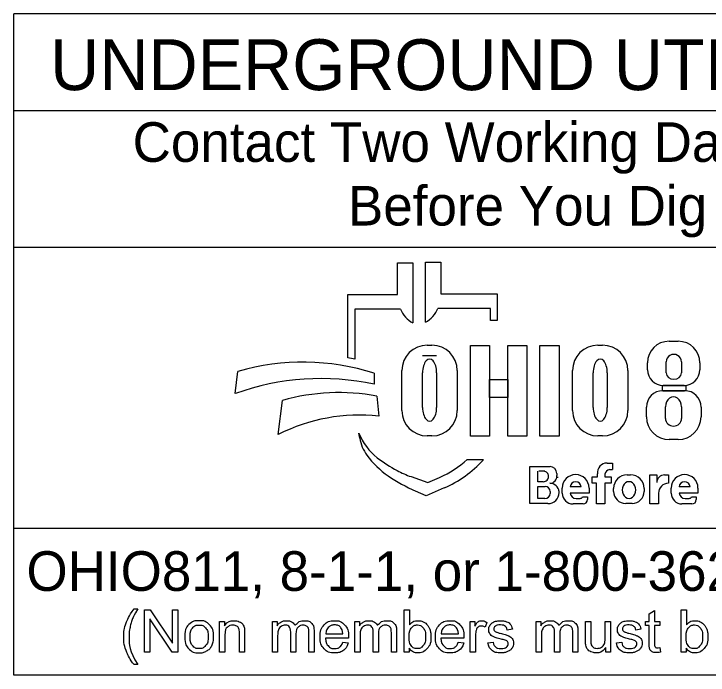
# Model space of a CAD drawing. Extents: x -0.3 to 41.5, y 0 to 22.
# Drawn here: x 2.978 to 5.431, y 2.345 to 4.682 of the extents above; entities that cross this region are included whole.
import ezdxf

# ---------------------------------------------------------------- set-up
doc = ezdxf.new("R2010")
doc.units = 0
doc.layers.add('GM_X_Section', color=7, linetype='Continuous')
doc.layers.add('SH_Cut_Line', color=7, linetype='Continuous')

msp = doc.modelspace()

# ---------------------------------------------------------------- linework, layer by layer
at = {"layer": 'GM_X_Section'}
for p, q in [((4.4329, 3.592), (4.4329, 3.8041)), ((4.4329, 3.8041), (4.4865, 3.8041)), ((4.4865, 3.8041), (4.4865, 3.6926)), ((4.3335, 3.6902), (4.3335, 3.8017)), ((4.3335, 3.8017), (4.3872, 3.8017)), ((4.3872, 3.8017), (4.3872, 3.5897)), ((4.1576, 3.4664), (4.1576, 3.6902)), ((4.1576, 3.6902), (4.3335, 3.6902)), ((4.4865, 3.6926), (4.6857, 3.6926)), ((4.6857, 3.6926), (4.6857, 3.5987)), ((4.1828, 3.6388), (4.1828, 3.4619)), ((4.3439, 3.6388), (4.1828, 3.6388)), ((4.6625, 3.6411), (4.4761, 3.6411)), ((4.6625, 3.5987), (4.6625, 3.6411)), ((4.6857, 3.5987), (4.6625, 3.5987)), ((4.4385, 3.5111), (4.4551, 3.5111)), ((5.0416, 3.5111), (5.0581, 3.5111)), ((5.2931, 3.5251), (5.3258, 3.5251)), ((4.4718, 3.474), (4.422, 3.474)), ((5.2168, 3.4244), (5.2168, 3.4487)), ((5.283, 3.4131), (5.283, 3.4524)), ((5.3371, 3.4524), (5.3371, 3.4131)), ((5.4022, 3.4487), (5.4022, 3.4244)), ((3.7602, 3.3401), (3.7696, 3.4182)), ((4.2509, 3.4117), (4.2509, 3.3729)), ((4.3491, 3.2796), (4.3491, 3.4216)), ((4.422, 3.291), (4.422, 3.4133)), ((4.4718, 3.4133), (4.4718, 3.291)), ((4.5445, 3.4216), (4.5445, 3.2796)), ((4.9521, 3.2796), (4.9521, 3.4216)), ((5.025, 3.291), (5.025, 3.4133)), ((5.0748, 3.4133), (5.0748, 3.291)), ((5.1476, 3.4216), (5.1476, 3.2796)), ((5.3462, 3.3684), (5.2728, 3.3684)), ((5.271, 3.3501), (5.3483, 3.3501)), ((3.912, 3.1955), (3.9267, 3.3157)), ((4.2608, 3.3311), (4.2671, 3.2601)), ((5.2131, 3.2582), (5.2131, 3.2923)), ((5.2806, 3.2523), (5.2806, 3.2932)), ((5.3374, 3.2932), (5.3374, 3.2523)), ((5.4062, 3.2923), (5.4062, 3.2582)), ((4.1997, 3.1826), (4.1967, 3.2005)), ((4.4551, 3.1901), (4.4385, 3.1901)), ((5.0581, 3.1901), (5.0416, 3.1901)), ((5.3252, 3.1773), (5.2941, 3.1773)), ((4.58, 3.1067), (4.6375, 3.1067)), ((5.0739, 3.0945), (5.0934, 3.0945)), ((5.0934, 3.0945), (5.0934, 3.0715)), ((4.8013, 2.951), (4.8013, 3.0817)), ((4.8013, 3.0817), (4.8725, 3.0817)), ((5.0934, 3.071), (5.0832, 3.071)), ((4.3816, 3.0464), (4.441, 3.0259)), ((4.441, 3.0259), (4.4821, 3.0437)), ((4.8293, 3.0282), (4.8293, 3.0652)), ((4.8545, 3.0652), (4.8332, 3.0652)), ((4.8963, 3.058), (4.8963, 3.0501)), ((5.0213, 3.0231), (5.0213, 3.0461)), ((5.0213, 3.0461), (5.0406, 3.0461)), ((5.0406, 3.0461), (5.0406, 3.0566)), ((5.0667, 3.0546), (5.0667, 3.0461)), ((5.0667, 3.0461), (5.0883, 3.0461)), ((5.0883, 3.0461), (5.0883, 3.0231)), ((5.1451, 3.0527), (5.1573, 3.0527)), ((5.2254, 2.9498), (5.2254, 3.0525)), ((5.2254, 3.0525), (5.2499, 3.0525)), ((5.2499, 3.0525), (5.2499, 3.0256)), ((5.2772, 3.0525), (5.291, 3.0525)), ((5.291, 3.0525), (5.291, 3.0228)), ((4.8487, 3.0282), (4.8293, 3.0282)), ((5.0362, 3.0231), (5.0213, 3.0231)), ((5.0362, 2.9498), (5.0362, 3.0231)), ((5.0883, 3.0231), (5.0667, 3.0231)), ((5.0667, 3.0231), (5.0667, 2.9498)), ((4.435, 2.9789), (4.3976, 2.9953)), ((4.4983, 3.0063), (4.435, 2.9789)), ((4.8293, 2.9688), (4.8293, 3.0117)), ((4.8293, 3.0117), (4.8548, 3.0117)), ((4.9159, 2.9878), (4.9159, 3.0062)), ((4.9824, 3.0102), (4.9439, 3.0102)), ((5.0104, 3.0062), (5.0104, 2.9885)), ((5.0973, 2.9941), (5.0973, 3.0049)), ((5.2051, 3.0049), (5.2051, 2.9941)), ((5.3008, 2.9878), (5.3008, 3.0062)), ((5.3674, 3.0102), (5.3288, 3.0102)), ((5.3953, 3.0062), (5.3953, 2.9885)), ((4.8729, 2.9936), (4.8729, 2.9872)), ((4.9043, 2.9907), (4.9043, 2.9903)), ((5.0104, 2.9885), (4.944, 2.9885)), ((4.9649, 2.9693), (4.979, 2.9693)), ((4.9876, 2.9748), (5.0045, 2.9748)), ((5.0045, 2.9748), (5.0045, 2.965)), ((5.2559, 2.9879), (5.2559, 2.9498)), ((5.3953, 2.9885), (5.3289, 2.9885)), ((5.3498, 2.9693), (5.3639, 2.9693)), ((5.3725, 2.9748), (5.3894, 2.9748)), ((5.3894, 2.9748), (5.3894, 2.965)), ((4.865, 2.951), (4.8013, 2.951)), ((4.8546, 2.9688), (4.8293, 2.9688)), ((4.9892, 2.9498), (4.9538, 2.9498)), ((5.0667, 2.9498), (5.0362, 2.9498)), ((5.1623, 2.9513), (5.1401, 2.9513)), ((5.2559, 2.9498), (5.2254, 2.9498)), ((5.3742, 2.9498), (5.3388, 2.9498))]:
    msp.add_line(p, q, dxfattribs=at)
for points in [[(4.591, 3.51), (4.6589, 3.51), (4.6589, 3.19), (4.591, 3.19)], [(4.7231, 3.51), (4.7911, 3.51), (4.7911, 3.19), (4.7231, 3.19)], [(4.8364, 3.51), (4.9052, 3.51), (4.9052, 3.19), (4.8364, 3.19)], [(4.6589, 3.3901), (4.7231, 3.3901), (4.7231, 3.3261), (4.6589, 3.3261)], [(5.2706, 3.3685), (5.3523, 3.3685), (5.3523, 3.35), (5.2706, 3.35)]]:
    msp.add_lwpolyline(points, close=True, dxfattribs=at)
for points in [[(3.4021, 2.5785), (3.4153, 2.5785)], [(3.4389, 2.4259), (3.4389, 2.576), (3.4592, 2.576), (3.5382, 2.4581), (3.5382, 2.576), (3.5572, 2.576), (3.5572, 2.4259), (3.5369, 2.4259), (3.4579, 2.5438), (3.4579, 2.4259), (3.4389, 2.4259)], [(4.3743, 2.4259), (4.3573, 2.4259), (4.3573, 2.576), (4.3757, 2.576), (4.3757, 2.5225)], [(5.2233, 2.4577), (5.2233, 2.5204), (5.2097, 2.5204), (5.2097, 2.5347), (5.2233, 2.5347), (5.2233, 2.5616), (5.2417, 2.5727), (5.2417, 2.5347), (5.2601, 2.5347), (5.2601, 2.5204), (5.2417, 2.5204), (5.2417, 2.4566)], [(5.3534, 2.4259), (5.3363, 2.4259), (5.3363, 2.576), (5.3548, 2.576), (5.3548, 2.5225)], [(3.7048, 2.4259), (3.7048, 2.5347), (3.7214, 2.5347), (3.7214, 2.5192)], [(3.8912, 2.4259), (3.8912, 2.5347), (3.9077, 2.5347), (3.9077, 2.5193)], [(4.1826, 2.4259), (4.1826, 2.5347), (4.1991, 2.5347), (4.1991, 2.5193)], [(4.5904, 2.4259), (4.5904, 2.5347), (4.607, 2.5347), (4.607, 2.5182)], [(4.6495, 2.5312), (4.643, 2.5142)], [(4.8236, 2.4259), (4.8236, 2.5347), (4.8401, 2.5347), (4.8401, 2.5193)], [(4.9979, 2.4673), (4.9979, 2.5347), (5.0164, 2.5347), (5.0164, 2.4744)], [(5.0676, 2.4764), (5.0676, 2.5347), (5.0861, 2.5347), (5.0861, 2.4259), (5.0696, 2.4259)], [(4.7394, 2.5066), (4.7213, 2.5041)], [(5.194, 2.5066), (5.1759, 2.5041)], [(3.7233, 2.4853), (3.7233, 2.4259), (3.7048, 2.4259)], [(3.7932, 2.4928), (3.7932, 2.4259), (3.7748, 2.4259), (3.7748, 2.492)], [(3.9097, 2.4823), (3.9097, 2.4259), (3.8912, 2.4259)], [(3.9743, 2.489), (3.9743, 2.4259), (3.9559, 2.4259), (3.9559, 2.4965)], [(4.0388, 2.5005), (4.0388, 2.4259), (4.0203, 2.4259), (4.0203, 2.4944)], [(4.0799, 2.4906), (4.1406, 2.4906)], [(4.201, 2.4823), (4.201, 2.4259), (4.1826, 2.4259)], [(4.2657, 2.489), (4.2657, 2.4259), (4.2473, 2.4259), (4.2473, 2.4965)], [(4.3301, 2.5005), (4.3301, 2.4259), (4.3117, 2.4259), (4.3117, 2.4944)], [(4.4879, 2.4906), (4.5486, 2.4906)], [(4.6088, 2.4829), (4.6088, 2.4259), (4.5904, 2.4259)], [(4.842, 2.4823), (4.842, 2.4259), (4.8236, 2.4259)], [(4.9067, 2.489), (4.9067, 2.4259), (4.8883, 2.4259), (4.8883, 2.4965)], [(4.9711, 2.5005), (4.9711, 2.4259), (4.9527, 2.4259), (4.9527, 2.4944)], [(4.16, 2.4755), (4.0788, 2.4755)], [(4.1404, 2.461), (4.1595, 2.4586)], [(4.568, 2.4755), (4.4868, 2.4755)], [(4.5484, 2.461), (4.5675, 2.4586)], [(4.653, 2.4584), (4.6712, 2.4612)], [(5.1076, 2.4584), (5.1258, 2.4612)], [(4.3743, 2.4395), (4.3743, 2.4259)], [(5.0696, 2.4259), (5.0696, 2.4419)], [(5.2601, 2.4423), (5.2628, 2.426)], [(5.3534, 2.4395), (5.3534, 2.4259)], [(3.4153, 2.3817), (3.4021, 2.3817)]]:
    msp.add_lwpolyline(points, dxfattribs=at)
for centre, radius, start, end in [((4.4353, 3.6756), 0.0985, 201.9296, 240.7469), ((4.3847, 3.6779), 0.0985, 299.2531, 338.0704), ((4.4385, 3.4216), 0.0895, 90, 180), ((4.4551, 3.4216), 0.0895, 0, 90), ((5.0416, 3.4216), 0.0895, 90, 180), ((5.0581, 3.4216), 0.0895, 0, 90), ((5.2931, 3.4487), 0.0763, 90, 180), ((5.3258, 3.4487), 0.0763, 0, 90), ((4.0295, 2.6574), 0.8191, 79.2074, 81.0007), ((3.9997, 2.6321), 0.8191, 72.1402, 106.3144), ((5.2728, 3.4244), 0.056, 180, 270), ((5.3462, 3.4244), 0.056, 270, 0), ((4.0628, 2.501), 0.8919, 77.8238, 109.8274), ((4.1267, 2.6113), 0.7322, 79.44, 105.8467), ((5.271, 3.2923), 0.0579, 90, 180), ((5.3483, 3.2923), 0.0579, 0, 90), ((4.1987, 2.6281), 0.6357, 83.8248, 116.8021), ((4.4385, 3.2796), 0.0895, 180, 270), ((4.4551, 3.2796), 0.0895, 270, 0), ((5.0416, 3.2796), 0.0895, 180, 270), ((5.0581, 3.2796), 0.0895, 270, 0), ((5.2941, 3.2582), 0.081, 180, 270), ((5.3252, 3.2582), 0.081, 270, 0), ((4.3841, 3.2726), 0.2008, 201.0457, 232.5314), ((4.341, 3.2067), 0.1433, 189.6817, 216.0884), ((4.4747, 3.3042), 0.3088, 216.0884, 235.7167), ((4.5766, 3.5239), 0.5173, 232.5314, 241.794), ((4.3387, 3.3742), 0.3602, 293.4582, 312.0712), ((4.3387, 3.3742), 0.401, 293.4582, 317.8286), ((5.0739, 3.061), 0.0335, 90, 187.5187), ((4.4914, 3.365), 0.3371, 241.794, 250.9821), ((4.8725, 3.058), 0.0238, 0, 90), ((5.0832, 3.0546), 0.0165, 90, 180), ((4.6412, 3.5484), 0.6044, 235.7167, 246.2325), ((4.8487, 3.047), 0.0187, 270, 2.0582), ((4.8505, 3.0483), 0.0169, 357.8325, 90), ((4.8721, 3.0472), 0.0243, 270, 6.6529), ((4.8827, 3.0458), 0.0175, 347.4023, 0), ((4.9631, 3.0062), 0.0473, 0, 180), ((5.1451, 3.0049), 0.0478, 90, 180), ((5.1573, 3.0049), 0.0478, 0, 90), ((5.2768, 3.0256), 0.0269, 89.2449, 180), ((5.3481, 3.0062), 0.0473, 0, 180), ((4.8722, 2.9908), 0.0321, 4.0748, 90), ((4.9632, 3.0092), 0.0193, 2.9632, 177.0368), ((5.2908, 2.9879), 0.0349, 89.6033, 180), ((5.3481, 3.0092), 0.0193, 2.9632, 177.0368), ((4.8548, 2.9936), 0.0181, 0, 90), ((4.8714, 2.9907), 0.033, 0, 11.7502), ((5.1401, 2.9941), 0.0428, 180, 270), ((5.1623, 2.9941), 0.0428, 270, 0), ((4.8546, 2.9872), 0.0184, 270, 0), ((4.865, 2.9903), 0.0393, 270, 0), ((4.9538, 2.9878), 0.038, 180, 270), ((4.9649, 2.9903), 0.021, 184.827, 270), ((4.979, 2.9787), 0.00938, 270, 335.9979), ((5.3388, 2.9878), 0.038, 180, 270), ((5.3498, 2.9903), 0.021, 184.827, 270), ((5.3639, 2.9787), 0.00938, 270, 335.9979), ((4.9892, 2.965), 0.0152, 270, 0), ((5.3742, 2.965), 0.0152, 270, 0)]:
    msp.add_arc(centre, radius, start, end, dxfattribs=at)
for centre, major_axis, ratio, start_param, end_param in [((4.4469, 3.4133), (0, 0.0484), 0.514403, 4.712389, 7.853982), ((5.0499, 3.4133), (0, 0.0484), 0.514403, 4.712389, 7.853982), ((5.31, 3.4524), (0.0271, 0), 0.969373, 0, 3.141593), ((5.31, 3.4131), (0.0271, 0), 0.818453, 3.141593, 6.283185), ((5.309, 3.2932), (0, 0.0358), 0.794529, 4.712389, 7.853982), ((4.4469, 3.291), (0, 0.0484), 0.514403, 1.570796, 4.712389), ((5.0499, 3.291), (0, 0.0484), 0.514403, 1.570796, 4.712389), ((5.309, 3.2523), (0.0284, 0), 0.959837, 3.141593, 6.283185), ((5.1517, 2.9995), (0, 0.029), 0.832186, 4.712389, 7.853982), ((5.1517, 2.9995), (0, 0.0302), 0.797287, 1.570796, 4.712389)]:
    msp.add_ellipse(centre, major_axis=major_axis, ratio=ratio, start_param=start_param, end_param=end_param, dxfattribs=at)
for points in [[(3.4021, 2.3817), (3.3869, 2.4009), (3.3763, 2.4268), (3.3657, 2.4526), (3.3657, 2.4802), (3.3657, 2.5046), (3.3736, 2.5269), (3.3829, 2.5528), (3.4021, 2.5785)], [(3.4153, 2.5785), (3.4029, 2.5572), (3.3989, 2.5481), (3.3927, 2.534), (3.3891, 2.5186), (3.3847, 2.4995), (3.3847, 2.4801), (3.3847, 2.4309), (3.4153, 2.3817)], [(3.5814, 2.4803), (3.5814, 2.5105), (3.5981, 2.525), (3.6122, 2.5371), (3.6323, 2.5371), (3.6547, 2.5371), (3.669, 2.5224), (3.6832, 2.5077), (3.6832, 2.4818), (3.6832, 2.4608), (3.6769, 2.4488), (3.6706, 2.4368), (3.6586, 2.4301), (3.6466, 2.4235), (3.6323, 2.4235), (3.6095, 2.4235), (3.5954, 2.4381), (3.5814, 2.4527), (3.5814, 2.4803)], [(3.7214, 2.5192), (3.7334, 2.5371), (3.756, 2.5371), (3.7659, 2.5371), (3.7741, 2.5336), (3.7823, 2.53), (3.7864, 2.5243), (3.7905, 2.5186), (3.7922, 2.5107), (3.7932, 2.5056), (3.7932, 2.4928)], [(3.9077, 2.5193), (3.9128, 2.5274), (3.9214, 2.5322), (3.9299, 2.5371), (3.9407, 2.5371), (3.9528, 2.5371), (3.9606, 2.5321), (3.9683, 2.527), (3.9715, 2.518), (3.9844, 2.5371), (4.0051, 2.5371), (4.0213, 2.5371), (4.03, 2.5281), (4.0388, 2.5192), (4.0388, 2.5005)], [(4.1595, 2.4586), (4.155, 2.4419), (4.1428, 2.4327), (4.1306, 2.4235), (4.1117, 2.4235), (4.0878, 2.4235), (4.0738, 2.4382), (4.0598, 2.4528), (4.0598, 2.4794), (4.0598, 2.5068), (4.074, 2.522), (4.0881, 2.5371), (4.1106, 2.5371), (4.1324, 2.5371), (4.1463, 2.5223), (4.1601, 2.5074), (4.1601, 2.4805), (4.1601, 2.4788), (4.16, 2.4755)], [(4.1991, 2.5193), (4.2042, 2.5274), (4.2127, 2.5322), (4.2212, 2.5371), (4.2321, 2.5371), (4.2442, 2.5371), (4.2519, 2.5321), (4.2597, 2.527), (4.2628, 2.518), (4.2758, 2.5371), (4.2965, 2.5371), (4.3127, 2.5371), (4.3214, 2.5281), (4.3301, 2.5192), (4.3301, 2.5005)], [(4.3757, 2.5225), (4.3874, 2.5371), (4.4055, 2.5371), (4.4155, 2.5371), (4.4245, 2.5331), (4.4335, 2.529), (4.4392, 2.5217), (4.445, 2.5144), (4.4483, 2.504), (4.4516, 2.4937), (4.4516, 2.4819), (4.4516, 2.454), (4.4378, 2.4387), (4.4239, 2.4235), (4.4046, 2.4235), (4.3853, 2.4235), (4.3743, 2.4395)], [(4.5675, 2.4586), (4.563, 2.4419), (4.5508, 2.4327), (4.5386, 2.4235), (4.5196, 2.4235), (4.4958, 2.4235), (4.4818, 2.4382), (4.4678, 2.4528), (4.4678, 2.4794), (4.4678, 2.5068), (4.482, 2.522), (4.4961, 2.5371), (4.5186, 2.5371), (4.5404, 2.5371), (4.5543, 2.5223), (4.5681, 2.5074), (4.5681, 2.4805), (4.5681, 2.4788), (4.568, 2.4755)], [(4.607, 2.5182), (4.6133, 2.5298), (4.6187, 2.5334), (4.6241, 2.5371), (4.6305, 2.5371), (4.6398, 2.5371), (4.6495, 2.5312)], [(4.6712, 2.4612), (4.6727, 2.4503), (4.6798, 2.4444), (4.6868, 2.4386), (4.6995, 2.4386), (4.7122, 2.4386), (4.7184, 2.4438), (4.7245, 2.4489), (4.7245, 2.4559), (4.7245, 2.4622), (4.7191, 2.4658), (4.7153, 2.4682), (4.7002, 2.472), (4.6799, 2.4771), (4.672, 2.4809), (4.6642, 2.4846), (4.6601, 2.4912), (4.6561, 2.4978), (4.6561, 2.5058), (4.6561, 2.5131), (4.6594, 2.5192), (4.6628, 2.5254), (4.6685, 2.5295), (4.6728, 2.5327), (4.6803, 2.5349), (4.6877, 2.5371), (4.6962, 2.5371), (4.709, 2.5371), (4.7187, 2.5334), (4.7284, 2.5297), (4.733, 2.5234), (4.7377, 2.5171), (4.7394, 2.5066)], [(4.8401, 2.5193), (4.8452, 2.5274), (4.8537, 2.5322), (4.8622, 2.5371), (4.8731, 2.5371), (4.8852, 2.5371), (4.8929, 2.5321), (4.9007, 2.527), (4.9038, 2.518), (4.9168, 2.5371), (4.9375, 2.5371), (4.9537, 2.5371), (4.9624, 2.5281), (4.9711, 2.5192), (4.9711, 2.5005)], [(5.1258, 2.4612), (5.1273, 2.4503), (5.1343, 2.4444), (5.1414, 2.4386), (5.154, 2.4386), (5.1668, 2.4386), (5.1729, 2.4438), (5.1791, 2.4489), (5.1791, 2.4559), (5.1791, 2.4622), (5.1736, 2.4658), (5.1698, 2.4682), (5.1548, 2.472), (5.1345, 2.4771), (5.1266, 2.4809), (5.1188, 2.4846), (5.1147, 2.4912), (5.1107, 2.4978), (5.1107, 2.5058), (5.1107, 2.5131), (5.114, 2.5192), (5.1173, 2.5254), (5.1231, 2.5295), (5.1274, 2.5327), (5.1348, 2.5349), (5.1423, 2.5371), (5.1508, 2.5371), (5.1636, 2.5371), (5.1733, 2.5334), (5.183, 2.5297), (5.1876, 2.5234), (5.1922, 2.5171), (5.194, 2.5066)], [(5.3548, 2.5225), (5.3664, 2.5371), (5.3846, 2.5371), (5.3946, 2.5371), (5.4036, 2.5331), (5.4125, 2.529), (5.4183, 2.5217), (5.4241, 2.5144), (5.4274, 2.504), (5.4306, 2.4937), (5.4306, 2.4819), (5.4306, 2.454), (5.4168, 2.4387), (5.403, 2.4235), (5.3836, 2.4235), (5.3644, 2.4235), (5.3534, 2.4395)], [(3.6003, 2.4803), (3.6003, 2.4594), (3.6094, 2.449), (3.6185, 2.4386), (3.6323, 2.4386), (3.646, 2.4386), (3.6551, 2.449), (3.6642, 2.4595), (3.6642, 2.4809), (3.6642, 2.5011), (3.6551, 2.5115), (3.6459, 2.5219), (3.6323, 2.5219), (3.6185, 2.5219), (3.6094, 2.5115), (3.6003, 2.5012), (3.6003, 2.4803)], [(3.7748, 2.492), (3.7748, 2.5033), (3.7726, 2.5089), (3.7705, 2.5144), (3.765, 2.5178), (3.7595, 2.5211), (3.7521, 2.5211), (3.7404, 2.5211), (3.7318, 2.5136), (3.7233, 2.5061), (3.7233, 2.4853)], [(3.9559, 2.4965), (3.9559, 2.5088), (3.9514, 2.5149), (3.9469, 2.5211), (3.9366, 2.5211), (3.9288, 2.5211), (3.9222, 2.517), (3.9156, 2.5129), (3.9126, 2.505), (3.9097, 2.4971), (3.9097, 2.4823)], [(4.0203, 2.4944), (4.0203, 2.5054), (4.0185, 2.5103), (4.0168, 2.5151), (4.012, 2.5181), (4.0073, 2.5211), (4.001, 2.5211), (3.9895, 2.5211), (3.9819, 2.5135), (3.9743, 2.5058), (3.9743, 2.489)], [(4.1406, 2.4906), (4.1394, 2.5044), (4.1337, 2.5113), (4.1249, 2.522), (4.1108, 2.522), (4.0981, 2.522), (4.0894, 2.5135), (4.0808, 2.5049), (4.0799, 2.4906)], [(4.2473, 2.4965), (4.2473, 2.5088), (4.2428, 2.5149), (4.2383, 2.5211), (4.228, 2.5211), (4.2202, 2.5211), (4.2136, 2.517), (4.207, 2.5129), (4.204, 2.505), (4.201, 2.4971), (4.201, 2.4823)], [(4.3117, 2.4944), (4.3117, 2.5054), (4.3099, 2.5103), (4.3081, 2.5151), (4.3034, 2.5181), (4.2987, 2.5211), (4.2923, 2.5211), (4.2809, 2.5211), (4.2733, 2.5135), (4.2657, 2.5058), (4.2657, 2.489)], [(4.3741, 2.4811), (4.3741, 2.4615), (4.3794, 2.4528), (4.3881, 2.4386), (4.4029, 2.4386), (4.415, 2.4386), (4.4238, 2.4491), (4.4326, 2.4596), (4.4326, 2.4804), (4.4326, 2.5017), (4.4241, 2.5119), (4.4157, 2.522), (4.4038, 2.522), (4.3917, 2.522), (4.3829, 2.5115), (4.3741, 2.501), (4.3741, 2.4811)], [(4.5486, 2.4906), (4.5474, 2.5044), (4.5417, 2.5113), (4.5328, 2.522), (4.5188, 2.522), (4.5061, 2.522), (4.4974, 2.5135), (4.4888, 2.5049), (4.4879, 2.4906)], [(4.643, 2.5142), (4.6363, 2.5181), (4.6295, 2.5181), (4.6235, 2.5181), (4.6187, 2.5145), (4.6139, 2.5108), (4.6119, 2.5044), (4.6088, 2.4945), (4.6088, 2.4829)], [(4.7213, 2.5041), (4.7201, 2.5126), (4.7142, 2.5173), (4.7083, 2.522), (4.6975, 2.522), (4.6848, 2.522), (4.6794, 2.5178), (4.6739, 2.5136), (4.6739, 2.5079), (4.6739, 2.5044), (4.6762, 2.5015), (4.6785, 2.4985), (4.6833, 2.4966), (4.686, 2.4955), (4.6996, 2.4918), (4.7192, 2.4866), (4.7269, 2.4833), (4.7347, 2.48), (4.7391, 2.4736), (4.7435, 2.4673), (4.7435, 2.4579), (4.7435, 2.4486), (4.7381, 2.4405), (4.7327, 2.4324), (4.7226, 2.4279), (4.7124, 2.4235), (4.6996, 2.4235), (4.6784, 2.4235), (4.6672, 2.4323), (4.6561, 2.4411), (4.653, 2.4584)], [(4.8883, 2.4965), (4.8883, 2.5088), (4.8838, 2.5149), (4.8793, 2.5211), (4.869, 2.5211), (4.8612, 2.5211), (4.8546, 2.517), (4.848, 2.5129), (4.845, 2.505), (4.842, 2.4971), (4.842, 2.4823)], [(4.9527, 2.4944), (4.9527, 2.5054), (4.9509, 2.5103), (4.9491, 2.5151), (4.9444, 2.5181), (4.9397, 2.5211), (4.9333, 2.5211), (4.9219, 2.5211), (4.9143, 2.5135), (4.9067, 2.5058), (4.9067, 2.489)], [(5.1759, 2.5041), (5.1747, 2.5126), (5.1688, 2.5173), (5.1629, 2.522), (5.1521, 2.522), (5.1394, 2.522), (5.1339, 2.5178), (5.1285, 2.5136), (5.1285, 2.5079), (5.1285, 2.5044), (5.1308, 2.5015), (5.133, 2.4985), (5.1378, 2.4966), (5.1406, 2.4955), (5.1542, 2.4918), (5.1737, 2.4866), (5.1815, 2.4833), (5.1893, 2.48), (5.1937, 2.4736), (5.1981, 2.4673), (5.1981, 2.4579), (5.1981, 2.4486), (5.1927, 2.4405), (5.1873, 2.4324), (5.1772, 2.4279), (5.167, 2.4235), (5.1542, 2.4235), (5.1329, 2.4235), (5.1218, 2.4323), (5.1107, 2.4411), (5.1076, 2.4584)], [(5.3532, 2.4811), (5.3532, 2.4615), (5.3585, 2.4528), (5.3672, 2.4386), (5.382, 2.4386), (5.3941, 2.4386), (5.4029, 2.4491), (5.4116, 2.4596), (5.4116, 2.4804), (5.4116, 2.5017), (5.4032, 2.5119), (5.3948, 2.522), (5.3828, 2.522), (5.3708, 2.522), (5.362, 2.5115), (5.3532, 2.501), (5.3532, 2.4811)], [(4.0788, 2.4755), (4.0799, 2.4576), (4.089, 2.4481), (4.0981, 2.4386), (4.1117, 2.4386), (4.1219, 2.4386), (4.1291, 2.4439), (4.1362, 2.4493), (4.1404, 2.461)], [(4.4868, 2.4755), (4.4879, 2.4576), (4.497, 2.4481), (4.5061, 2.4386), (4.5197, 2.4386), (4.5299, 2.4386), (4.537, 2.4439), (4.5442, 2.4493), (4.5484, 2.461)], [(5.0696, 2.4419), (5.0569, 2.4235), (5.0351, 2.4235), (5.0255, 2.4235), (5.0171, 2.4272), (5.0088, 2.4308), (5.0047, 2.4364), (5.0007, 2.442), (4.9991, 2.4501), (4.9979, 2.4555), (4.9979, 2.4673)], [(5.0164, 2.4744), (5.0164, 2.46), (5.0175, 2.4549), (5.0192, 2.4477), (5.0249, 2.4435), (5.0305, 2.4394), (5.0388, 2.4394), (5.0471, 2.4394), (5.0543, 2.4436), (5.0616, 2.4479), (5.0646, 2.4552), (5.0676, 2.4625), (5.0676, 2.4764)], [(5.2628, 2.426), (5.255, 2.4244), (5.2488, 2.4244), (5.2388, 2.4244), (5.2333, 2.4276), (5.2278, 2.4307), (5.2255, 2.4359), (5.2233, 2.4411), (5.2233, 2.4577)], [(5.2417, 2.4566), (5.2417, 2.4487), (5.2427, 2.4465), (5.2436, 2.4442), (5.2458, 2.4429), (5.248, 2.4415), (5.2521, 2.4415), (5.2551, 2.4415), (5.2601, 2.4423)]]:
    msp.add_open_spline(points, degree=3, dxfattribs=at)
at = {"layer": 'SH_Cut_Line'}
for p, q in [((2.9775, 2.3447), (2.9775, 4.6822)), ((7.2275, 4.6822), (2.9775, 4.6822)), ((2.9775, 4.3407), (7.2275, 4.3407)), ((2.9775, 3.8573), (7.2275, 3.8573)), ((7.2275, 2.8626), (2.9775, 2.8626)), ((7.2275, 2.3447), (2.9775, 2.3447))]:
    msp.add_line(p, q, dxfattribs=at)

# ---------------------------------------------------------------- texts
at = {"layer": 'GM_X_Section'}
for s, height, p in [('UNDERGROUND UTILITIES', 0.18, (3.1057, 4.4126)), ('Contact Two Working Days', 0.14, (3.3972, 4.1591)), ('Before You Dig', 0.14, (4.1583, 3.9341)), ('OHIO811, 8-1-1, or 1-800-362-2764', 0.14, (3.022, 2.6426))]:
    msp.add_text(s, height=height, dxfattribs=at).set_placement(p)

doc.saveas('drawing.dxf')
